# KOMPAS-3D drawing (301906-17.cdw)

Views: Вид 8, Вид 9, Вид 10
Referenced files: Вал.cdw
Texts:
  Вал
  Петров С.А.
  СПБГТИ(ТУ)
  Текст на чертеже
  Размерные надписи
  Шероховатость
  Линия-выноска #1
  Линия-выноска #2
  Линия-выноска #3
  Отклонения формы и база
  Заголовок таблицы
  Ячейка таблицы
  Стрелка вида
  Обозначение изменения
  Фигурная скобка
  Номер узла
  Марка координационной оси
  VRCb
  Выносная надпись
  Обозначение узла
  Марка/позиционное обозначение с линией-выноской
  Марка/позиционное обозначение на линии
  Марка/позиционное обозначение без линии-выноски
  Ra 2,5
  Ra 1,6
  Ra 6,3
  js9
  Основной вид
  max
  Js9
  1. Неуказанные предельные отклонения размеров валов h14,
  отверстий H14, остальных   IT 14/2
  Шпоночный паз под мешалку
  Ra 12,5
  Гайка М48 ГОСТ 15522-70
  Гайка
  ГОСТ
  Баранов Д.А.
  группа 364
  Сталь 12Х18Н10Т  Круг
Dimensions and other numbers on the sheet: 105.11.00.00.001; 7; 63; 73; 48; 30; 3; 65; 105; 0,025; 1,6; 0,004; 5; 5,5; 45; 0,2; 0,5; 0,25; 4; 42,6; -6H; 70; 0,448428; 1:5; 1; 54.65; 105.11.00.00.001-; 0; 2; 6; 8; 9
